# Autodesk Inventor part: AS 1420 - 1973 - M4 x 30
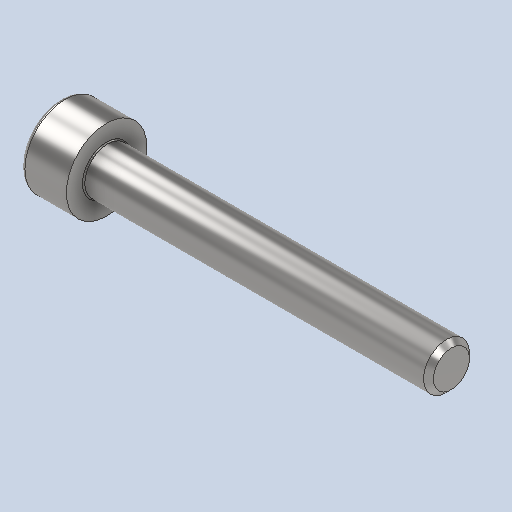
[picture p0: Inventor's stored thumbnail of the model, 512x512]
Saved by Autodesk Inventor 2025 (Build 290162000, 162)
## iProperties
Created: 2024-01
Part Number: AS 1420 - 1973 - M4 x 30
Material: Acciaio, Dolce
Description: Viti con esagono incassato metriche ISO
Document SubType Name: Modeling
Designer: Ryzen5700u
Density: 7.85 g/cm^3
Appearance: Default
Author: Ryzen5700u
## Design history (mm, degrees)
feature "Solid1"
node "Solido1"
